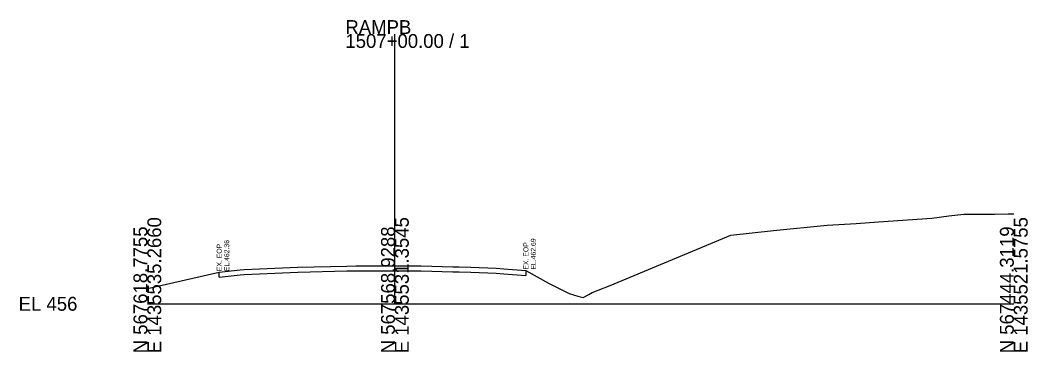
# Model space of a CAD drawing. Extents: x 1431908 to 1449087, y 567604 to 577825.
# Drawn here: x 1440484.4 to 1440688, y 573548.6 to 573615.5 of the extents above; entities that cross this region are included whole.
import ezdxf

# ---------------------------------------------------------------- set-up
doc = ezdxf.new("R2010")
doc.units = 0
for name, color, linetype in [('DESIGN - SHEET - Light Grid', 7, 'Continuous'), ('SURVEY - GROUND - Existing Pavement Layer', 7, 'Continuous'), ('SURVEY - GROUND - Existing Pavement Text', 7, 'Continuous'), ('SURVEY - GROUND - Top of Ground', 7, 'Continuous')]:
    doc.layers.add(name, color=color, linetype=linetype)

msp = doc.modelspace()

# ---------------------------------------------------------------- linework, layer by layer
at = {"layer": 'DESIGN - SHEET - Light Grid'}
for p, q in [((1440560.12, 573558.33), (1440560.12, 573612.75)), ((1440510.12, 573558.33), (1440560.12, 573558.33)), ((1440560.12, 573558.33), (1440685.12, 573558.33))]:
    msp.add_line(p, q, dxfattribs=at)
at = {"layer": 'SURVEY - GROUND - Existing Pavement Layer'}
for p, q in [((1440524.64, 573563.7), (1440524.64, 573564.7)), ((1440524.64, 573563.7), (1440528.86, 573564.18)), ((1440528.86, 573564.18), (1440529.67, 573564.22)), ((1440529.67, 573564.22), (1440540.54, 573564.7)), ((1440540.54, 573564.7), (1440550.41, 573564.95)), ((1440550.41, 573564.95), (1440552.23, 573565)), ((1440552.23, 573565), (1440554.45, 573565)), ((1440554.45, 573565), (1440560.12, 573564.99)), ((1440560.12, 573564.99), (1440565.45, 573564.98)), ((1440565.45, 573564.98), (1440571.84, 573564.8)), ((1440571.84, 573564.8), (1440573.09, 573564.77)), ((1440573.09, 573564.77), (1440575.44, 573564.7)), ((1440575.44, 573564.7), (1440580.58, 573564.53)), ((1440580.58, 573564.53), (1440582.09, 573564.4)), ((1440582.09, 573564.4), (1440586.58, 573564.02)), ((1440586.58, 573565.02), (1440586.58, 573564.02))]:
    msp.add_line(p, q, dxfattribs=at)
at = {"layer": 'SURVEY - GROUND - Top of Ground'}
msp.add_lwpolyline([(1440510.12, 573561.4), (1440524.64, 573564.7), (1440528.86, 573565.18), (1440529.67, 573565.22), (1440540.54, 573565.7), (1440550.41, 573565.95), (1440552.23, 573566), (1440554.45, 573566), (1440560.12, 573565.99), (1440565.45, 573565.98), (1440571.84, 573565.8), (1440573.09, 573565.77), (1440575.44, 573565.7), (1440580.58, 573565.53), (1440582.09, 573565.4), (1440586.58, 573565.02), (1440591.11, 573562.48), (1440595.33, 573560.43), (1440597.1, 573559.89), (1440598.14, 573559.58), (1440599.28, 573560.2), (1440599.97, 573560.63), (1440603.61, 573562.04), (1440627.98, 573572.18), (1440636.59, 573573.1), (1440647.42, 573574.22), (1440653.28, 573574.53), (1440657.8, 573574.84), (1440668.55, 573575.57), (1440672.03, 573576.06), (1440675.01, 573576.44), (1440678.33, 573576.42), (1440681.3, 573576.4), (1440684.01, 573576.45), (1440685.12, 573576.47)], dxfattribs=at)

# ---------------------------------------------------------------- texts
at = {"layer": 'DESIGN - SHEET - Light Grid'}
for s, p in [('RAMPB', (1440550.12, 573612.75)), ('1507+00.00 / 1', (1440550.12, 573609.95)), ('EL 456', (1440484.12, 573556.93))]:
    msp.add_text(s, height=2.8, dxfattribs=at).set_placement(p)
for s, p in [('E 1435535.2660', (1440512.92, 573548.33)), ('E 1435531.3545', (1440562.92, 573548.33)), ('E 1435521.5755', (1440687.92, 573548.33)), ('N 567618.7755', (1440510.12, 573548.33)), ('N 567568.9288', (1440560.12, 573548.33)), ('N 567444.3119', (1440685.12, 573548.33))]:
    msp.add_text(s, height=2.8, rotation=90, dxfattribs=at).set_placement(p)
at = {"layer": 'SURVEY - GROUND - Existing Pavement Text'}
for s, p in [('EL.462.69', (1440588.58, 573565.22)), ('EX. EOP', (1440525.14, 573564.9)), ('EL.462.36', (1440526.66, 573564.9)), ('EX. EOP', (1440587.08, 573565.22))]:
    msp.add_text(s, height=1, rotation=90, dxfattribs=at).set_placement(p)

doc.saveas('drawing.dxf')
